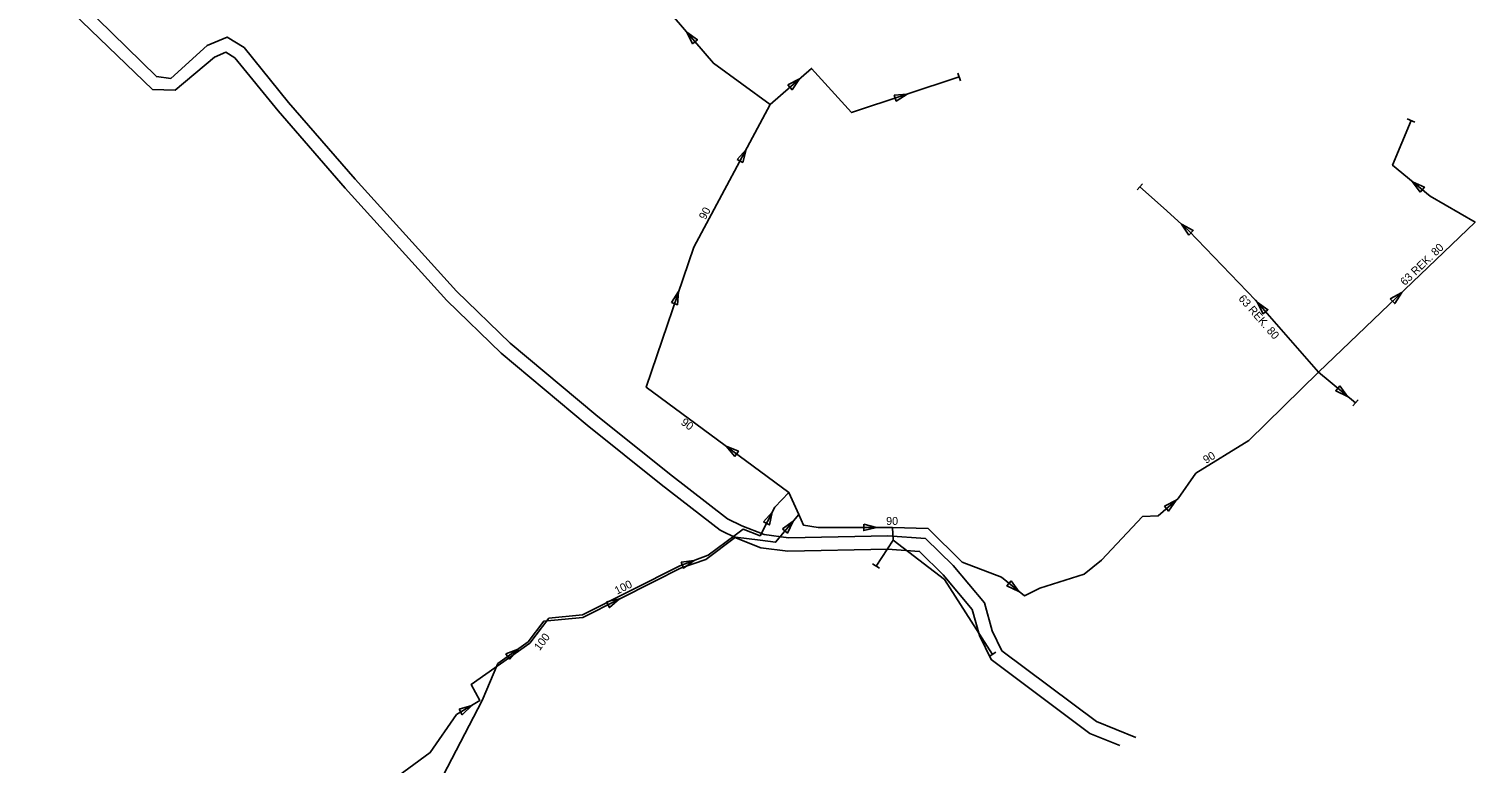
# Model space of a CAD drawing. Extents: x -444868 to -433212, y -1135421 to -1129859.
# Drawn here: x -442568 to -440760, y -1132115 to -1131197 of the extents above; entities that cross this region are included whole.
import ezdxf

# ---------------------------------------------------------------- set-up
doc = ezdxf.new("R2010")
doc.units = 0
doc.layers.add('Vrstva 3', color=7, linetype='Continuous')
doc.layers.add('Vrstva 53', color=7, linetype='Continuous')

msp = doc.modelspace()

# ---------------------------------------------------------------- linework, layer by layer
at = {"layer": 'Vrstva 3'}
for p, q in [((-441406.6, -1131252.2), (-441403.5, -1131261.7)), ((-440835.7, -1131313.4), (-440845, -1131309.6)), ((-441182.4, -1131398.1), (-441175.7, -1131390.7)), ((-440906.5, -1131660.7), (-440912.8, -1131668.4)), ((-441504.7, -1131871.4), (-441513.1, -1131865.9)), ((-441359, -1131976.4), (-441367.4, -1131981.8))]:
    msp.add_line(p, q, dxfattribs=at)
for points in [[(-442119.6, -1132140.9), (-442065.9, -1132101.8), (-442033.1, -1132054.2), (-442004, -1132036.6), (-442015, -1132016.8), (-441941.6, -1131965.1), (-441917.7, -1131933.9), (-441875.7, -1131929.5), (-441753.9, -1131868.4), (-441718.6, -1131855.1), (-441685, -1131829.8), (-441675, -1131822.5), (-441653.8, -1131830.7), (-441635.2, -1131794.8), (-441617.7, -1131776.6), (-441796.3, -1131644.7), (-441736.6, -1131469.8), (-441641.2, -1131291.5), (-441712.2, -1131239.9), (-441848.9, -1131080.2), (-441402.5, -1130760.5), (-441374.1, -1130710.5)], [(-441641.2, -1131291.5), (-441589.5, -1131246.4), (-441539.4, -1131301.5), (-441405.1, -1131256.9)], [(-440956, -1131626.2), (-440760.2, -1131438.6), (-440816.5, -1131406.1), (-440863.4, -1131367.5), (-440840.3, -1131311.5)], [(-441617.7, -1131776.6), (-441605.5, -1131804), (-441599.5, -1131817.5), (-441581.2, -1131820.5), (-441488.2, -1131820.2), (-441443.6, -1131821.8), (-441401.2, -1131863.7), (-441352.1, -1131882.5), (-441323.4, -1131905.8), (-441304, -1131896.3), (-441248.7, -1131878.9), (-441227.1, -1131861.3), (-441176, -1131806.8), (-441156.3, -1131805.9), (-441131.2, -1131784), (-441109.1, -1131752.3), (-441043, -1131711.5), (-440956, -1131626.2), (-441034.8, -1131536.2), (-441118.1, -1131449.4), (-441149.8, -1131420.8), (-441179.1, -1131394.4)], [(-440956, -1131626.2), (-440909.7, -1131664.5)], [(-441617, -1131778.6), (-441617.7, -1131776.6)], [(-442409.6, -1132541), (-442397.8, -1132526.2), (-442330.3, -1132448.5), (-442191.9, -1132283.9), (-442123.3, -1132253.5), (-442081.7, -1132211.5), (-442076.9, -1132182.7), (-442001.2, -1132036.6), (-441981.7, -1131990.4), (-441943.6, -1131963.5), (-441924.1, -1131937.6), (-441875.2, -1131932.7), (-441786, -1131887.8), (-441753.1, -1131871.4), (-441721.7, -1131860.3), (-441684.6, -1131832.3), (-441653.5, -1131836.3), (-441634.4, -1131838.9), (-441605.5, -1131804)], [(-441488.2, -1131820.2), (-441487.6, -1131836.4), (-441423.3, -1131885.2), (-441363.2, -1131979.1)], [(-441487.6, -1131836.4), (-441508.9, -1131868.7)]]:
    msp.add_lwpolyline(points, dxfattribs=at)
for points in [[(-441738.1, -1131215.8), (-441732.1, -1131210.6), (-441745.5, -1131201)], [(-441619.1, -1131266.9), (-441613.8, -1131273), (-441604.4, -1131259.4)], [(-441486.2, -1131279.7), (-441483.7, -1131287.3), (-441469.8, -1131278.4)], [(-441682.4, -1131360.1), (-441675.4, -1131363.9), (-441671.3, -1131347.9)], [(-440828.7, -1131401.2), (-440823.6, -1131395), (-440838.5, -1131388)], [(-441117.9, -1131455), (-441112.5, -1131449.1), (-441127.1, -1131441.3)], [(-441764.5, -1131539.2), (-441757, -1131541.8), (-441755.6, -1131525.4)], [(-441025.1, -1131553.4), (-441019.1, -1131548.1), (-441032.6, -1131538.7)], [(-440866.2, -1131534.6), (-440860.6, -1131540.4), (-440851.8, -1131526.4)], [(-440929.3, -1131643.1), (-440934.4, -1131649.3), (-440919.5, -1131656.4)], [(-441685.5, -1131731.5), (-441680.8, -1131725), (-441696, -1131718.7)], [(-441148.5, -1131793.8), (-441143.2, -1131799.8), (-441133.8, -1131786.3)], [(-441649.3, -1131813.4), (-441642.2, -1131817.1), (-441638.5, -1131801)], [(-441625.8, -1131822.2), (-441619.6, -1131827.3), (-441612.5, -1131812.5)], [(-441524.3, -1131816.3), (-441524.3, -1131824.3), (-441508.3, -1131820.3)], [(-441752.4, -1131863.5), (-441749.6, -1131871), (-441736, -1131861.6)], [(-441340.2, -1131887.1), (-441345.2, -1131893.3), (-441330.3, -1131900.3)], [(-441845.6, -1131913.3), (-441842, -1131920.5), (-441829.5, -1131909.7)], [(-441971.5, -1131978.3), (-441966.9, -1131984.9), (-441956.1, -1131972.4)], [(-442030, -1132047.6), (-442025.9, -1132054.5), (-442014.2, -1132042.8)]]:
    msp.add_lwpolyline(points, close=True, dxfattribs=at)
at = {"layer": 'Vrstva 53'}
for points in [[(-441204.3, -1132093), (-441241.8, -1132077.8), (-441364.8, -1131985.5), (-441379.4, -1131955.3), (-441388.6, -1131922.7), (-441424.9, -1131879.4), (-441454.5, -1131850.3), (-441494.7, -1131847.5), (-441619.3, -1131850), (-441652.9, -1131845.6), (-441683.1, -1131833.7), (-441703.5, -1131823.8), (-441777.5, -1131766.6), (-441869.7, -1131692.3), (-441977.3, -1131602.6), (-442045.1, -1131536.4), (-442172.3, -1131396.1), (-442256, -1131299.6), (-442310, -1131233.2), (-442321.3, -1131226.1), (-442335.7, -1131232.2), (-442384.7, -1131273.5), (-442412.9, -1131272.8), (-442567.5, -1131123.6)], [(-442555.9, -1131111.4), (-442408.1, -1131256.6), (-442390.3, -1131259.1), (-442344.6, -1131217.8), (-442319.8, -1131207.2), (-442298.7, -1131220.4), (-442243.2, -1131288.8), (-442159.7, -1131385), (-442033, -1131524.8), (-441966.1, -1131590.1), (-441859, -1131679.3), (-441767.1, -1131753.4), (-441694.7, -1131809.5), (-441676.4, -1131818.3), (-441648.7, -1131829.2), (-441618.4, -1131833.2), (-441494.3, -1131830.6), (-441447.1, -1131834), (-441412.6, -1131868), (-441373.4, -1131914.7), (-441363.6, -1131949.4), (-441351.5, -1131974.5), (-441233.4, -1132063), (-441184.4, -1132082.9)]]:
    msp.add_lwpolyline(points, dxfattribs=at)

# ---------------------------------------------------------------- texts
at = {"layer": 'Vrstva 3'}
for s, rotation, p in [('90', 61.8371, (-441722.1, -1131436.4)), ('63 REK. 80', 43.7783, (-440848, -1131518.6)), ('63 REK. 80', 311.1977, (-441056.6, -1131534.6)), ('90', 323.5594, (-441753.6, -1131690.7)), ('90', 31.7534, (-441096.4, -1131741)), ('90', 0.1841, (-441496.2, -1131817.2)), ('100', 26.6497, (-441832.5, -1131904.5)), ('100', 52.547, (-441929.3, -1131975.1))]:
    msp.add_text(s, height=10, rotation=rotation, dxfattribs=at).set_placement(p)

doc.saveas('drawing.dxf')
